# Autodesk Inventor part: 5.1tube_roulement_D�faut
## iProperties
Created: 2011-01
Part Number: 5.1tube_roulement_D�faut
Document SubType Name: Modeling
Designer: eric
Density: 1 g/cm^3
Mass: 8.49487 g
Surface Area: 103.044 cm^2
Volume: 8.49487 cm^3
Author: eric
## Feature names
1. Base1
